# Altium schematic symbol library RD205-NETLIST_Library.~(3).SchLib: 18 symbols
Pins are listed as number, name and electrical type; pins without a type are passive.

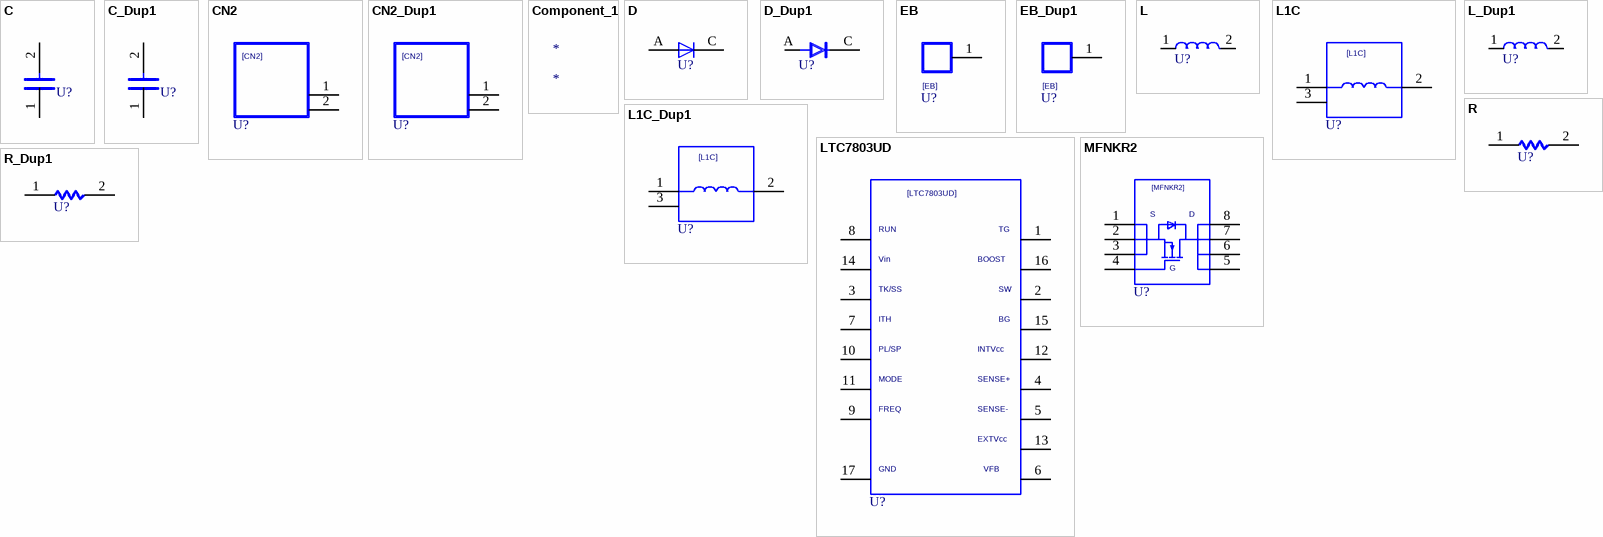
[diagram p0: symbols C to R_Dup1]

## C
designator U?  (value not drawn)
OriginalSymbolOrigin: (2540,7620); Altium-Right: 20; Altium-Bottom: 10
pins: 1, 2

## C_Dup1
designator U?, comment C  (value not drawn)
OriginalSymbolOrigin: (2540,7620); Altium-Right: 20; Altium-Bottom: 10
pins: 1, 2

## CN2
designator U?  (value not drawn)
OriginalSymbolOrigin: (2540,15240); Altium-Right: 50; Altium-Bottom: 60
pins: 1, 2

## CN2_Dup1
designator U?, comment CN2  (value not drawn)
OriginalSymbolOrigin: (2540,15240); Altium-Right: 50; Altium-Bottom: 60
pins: 1, 2

## Component_1
designator *

## D
designator U?  (value not drawn)
SAVEAREA0: -225,-91,12804,7836; SAVECOUNT: 3; TIME: 14:49:55; UPDATEUSER: 19870035; UPDATETIME: 14:20:16; OriginalSymbolOrigin: (5080,5080); Altium-Right: 10; Altium-Bottom: 20
pins: A, C

## D_Dup1
designator U?, comment D  (value not drawn)
SAVEAREA0: -565,-171,12979,8058; SAVECOUNT: 1; OriginalSymbolOrigin: (2540,5080); Altium-Right: 20
pins: A, C

## EB
designator U?  (value not drawn)
OriginalSymbolOrigin: (2540,12700); Altium-Right: 20
pins: 1

## EB_Dup1
designator U?, comment EB  (value not drawn)
OriginalSymbolOrigin: (2540,12700); Altium-Right: 20
pins: 1

## L
designator U?  (value not drawn)
OriginalSymbolOrigin: (2540,5080); Altium-Right: 30; Altium-Bottom: 20
pins: 1, 2

## L1C
designator U?  (value not drawn)
SAVECOUNT: 6; SAVEAREA0: -5636,-341,27978,18652; OriginalSymbolOrigin: (5080,15240); Altium-Right: 50
pins: 1, 2, 3

## L1C_Dup1
designator U?, comment L1C  (value not drawn)
SAVECOUNT: 6; SAVEAREA0: -5636,-341,27978,18652; OriginalSymbolOrigin: (5080,15240); Altium-Right: 50
pins: 1, 2, 3

## L_Dup1
designator U?, comment L  (value not drawn)
OriginalSymbolOrigin: (2540,5080); Altium-Right: 30; Altium-Bottom: 20
pins: 1, 2

## LTC7803UD
designator U?  (value not drawn)
SAVECOUNT: 29; SAVEAREA0: -53177,0,89020,58420; TIME: 16:14:14; UPDATEUSER: q91866sr; UPDATETIME: 13:15:36; OriginalSymbolOrigin: (5080,55880); Altium-Right: 100; Altium-Bottom: 210
pins: 1, 2, 3, 4, 5, 6, 7, 8, 9, 10, 11, 12, 13, 14, 15, 16, 17

## MFNKR2
designator U?  (value not drawn)
SAVEAREA0: -9199,-39,32138,22820; TIME: 18:57:44; UPDATEUSER: q91866sr; UPDATETIME: 12:36:02; SAVECOUNT: 10; OriginalSymbolOrigin: (5080,20320); Altium-Right: 50; Altium-Bottom: 70
pins: 1, 2, 3, 4, 5, 6, 7, 8

## R
designator U?  (value not drawn)
OriginalSymbolOrigin: (5080,5080); Altium-Right: 20
pins: 1, 2

## R_Dup1
designator U?, comment R  (value not drawn)
OriginalSymbolOrigin: (5080,5080); Altium-Right: 20
pins: 1, 2

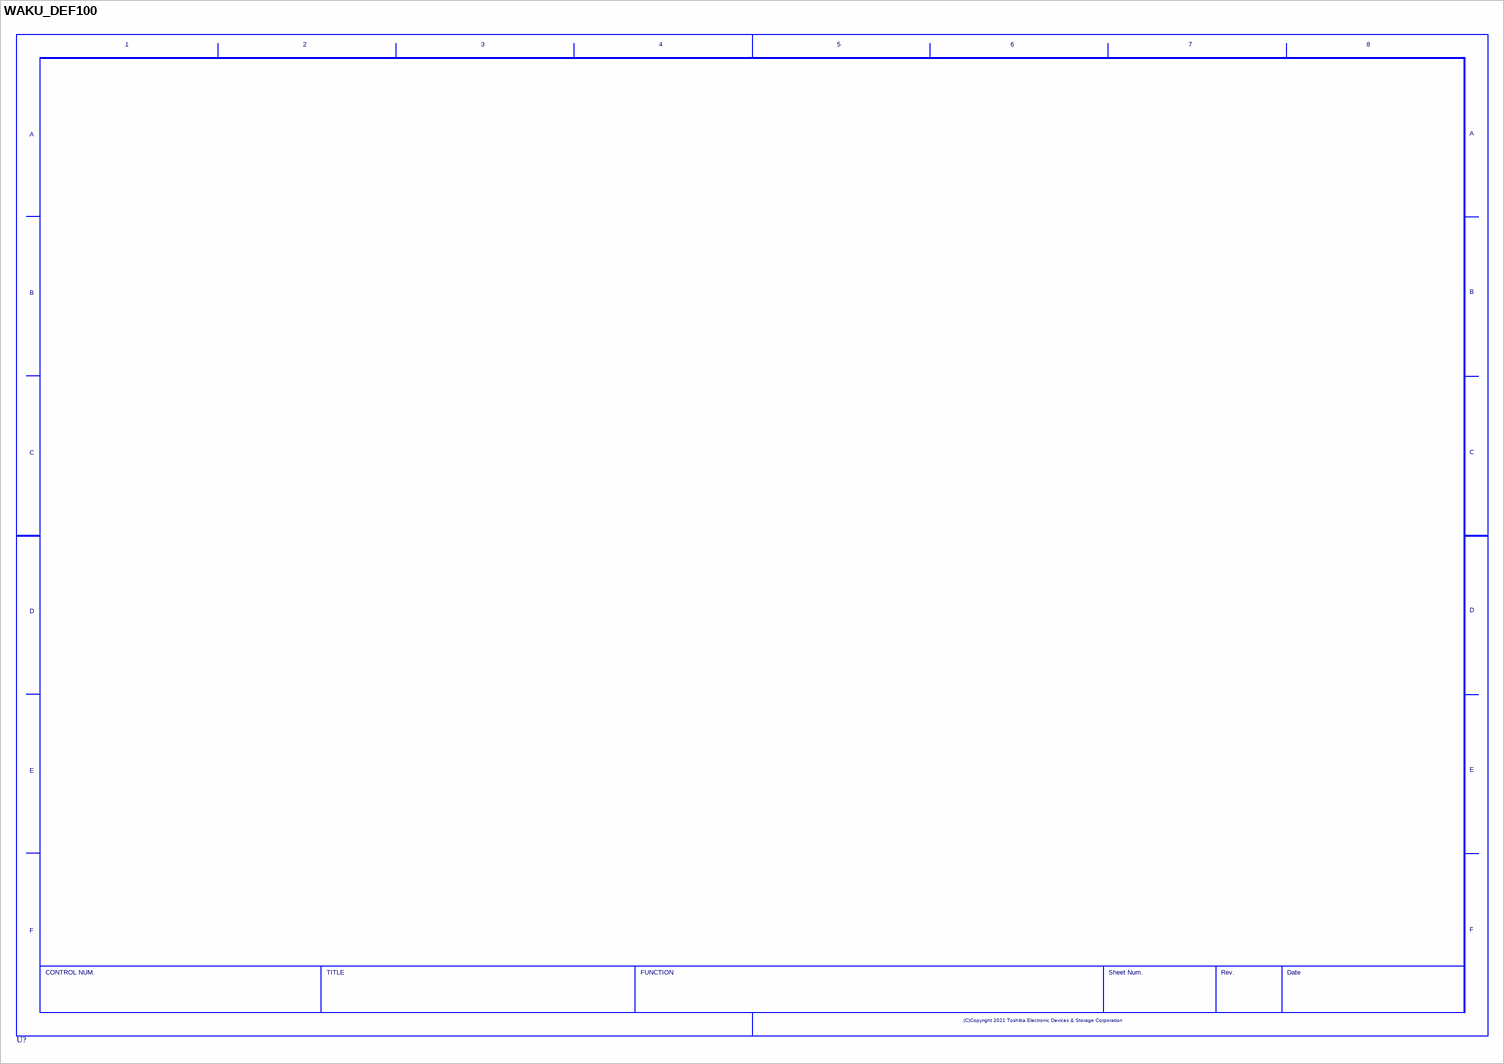
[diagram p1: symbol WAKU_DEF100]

## WAKU_DEF100
designator U?  (value not drawn)
PLOTTIME: HH:MM; SAVEAREA0: 148187,-66180,486823,89919; TIME: 14:30:25; UPDATEUSER: t5459927; UPDATETIME: 11:46:11; SAVECOUNT: 6; OriginalSymbolOrigin: (10160,284480); Altium-Right: 1570; Altium-Bottom: 1070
